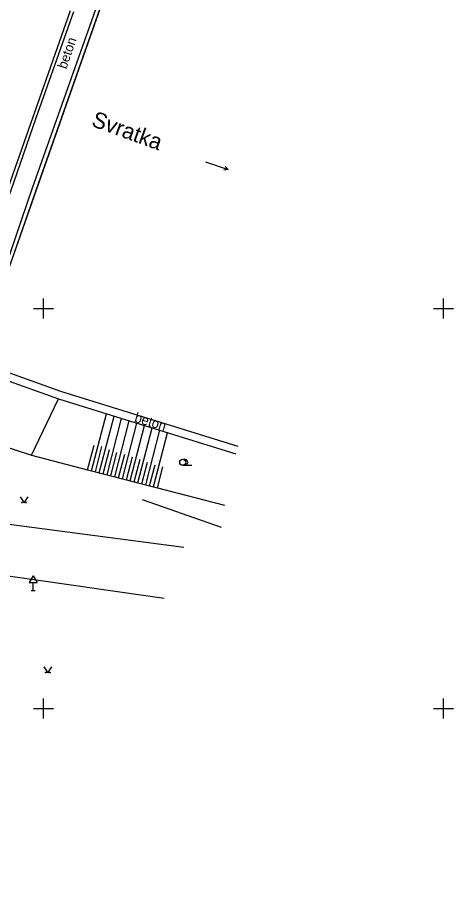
# Model space of a CAD drawing. Extents: x -599151 to -598424, y -1163476 to -1161924.
# Drawn here: x -598551.6 to -598524.4, y -1162086.9 to -1162031.8 of the extents above; entities that cross this region are included whole.
import ezdxf

# ---------------------------------------------------------------- set-up
doc = ezdxf.new("R2010")
doc.units = 0
for name, color, linetype in [('Vrstva 14', 7, 'Continuous'), ('Vrstva 17', 7, 'Continuous'), ('Vrstva 19', 7, 'Continuous'), ('Vrstva 22', 7, 'Continuous'), ('Vrstva 40', 7, 'Continuous'), ('Vrstva 41', 7, 'Continuous'), ('Vrstva 42', 7, 'Continuous'), ('Vrstva 49', 7, 'Continuous'), ('Vrstva 62', 7, 'Continuous'), ('Vrstva 63', 7, 'Continuous'), ('Vrstva 7', 7, 'Continuous')]:
    doc.layers.add(name, color=color, linetype=linetype)

msp = doc.modelspace()

# ---------------------------------------------------------------- linework, layer by layer
at = {"layer": 'Vrstva 14'}
msp.add_line((-598541.292, -1162059.805), (-598540.73, -1162059.805), dxfattribs=at)
for points in [[(-598551.464, -1162061.786), (-598551.214, -1162062.161), (-598550.964, -1162061.786)], [(-598549.981, -1162072.407), (-598549.731, -1162072.782), (-598549.481, -1162072.407)]]:
    msp.add_lwpolyline(points, dxfattribs=at)
for centre, radius in [((-598541.292, -1162059.617), 0.188), ((-598551.339, -1162062.136), 0.025), ((-598551.089, -1162062.136), 0.025), ((-598549.856, -1162072.757), 0.025), ((-598549.606, -1162072.757), 0.025)]:
    msp.add_circle(centre, radius, dxfattribs=at)
msp.add_arc((-598541.167, -1162059.617), 0.188, 249.4944, 109.0474, dxfattribs=at)
at = {"layer": 'Vrstva 17'}
for points in [[(-598537.83, -1162058.62), (-598548.91, -1162055.19), (-598554.206, -1162053.285)], [(-598554.367, -1162053.745), (-598549.065, -1162055.653), (-598537.974, -1162059.086)]]:
    msp.add_lwpolyline(points, dxfattribs=at)
at = {"layer": 'Vrstva 19'}
for p, q in [((-598550.65, -1162066.707), (-598550.9, -1162067.14)), ((-598550.65, -1162066.707), (-598550.4, -1162067.14)), ((-598550.9, -1162067.14), (-598550.4, -1162067.14)), ((-598550.775, -1162067.64), (-598550.525, -1162067.64)), ((-598550.65, -1162067.64), (-598550.65, -1162067.14))]:
    msp.add_line(p, q, dxfattribs=at)
at = {"layer": 'Vrstva 22'}
for points in [[(-598542.48, -1162019.53), (-598543.17, -1162021.17), (-598550.71, -1162042.47), (-598557.07, -1162061.1)], [(-598543.82, -1162061.94), (-598538.883, -1162063.667)]]:
    msp.add_lwpolyline(points, dxfattribs=at)
at = {"layer": 'Vrstva 40'}
msp.add_line((-598539.861, -1162040.821), (-598538.446, -1162041.319), dxfattribs=at)
msp.add_lwpolyline([(-598538.641, -1162041.118), (-598538.446, -1162041.319), (-598538.724, -1162041.354)], dxfattribs=at)
at = {"layer": 'Vrstva 41'}
for points in [[(-598546.994, -1162060.146), (-598546.066, -1162056.581)], [(-598546.51, -1162060.272), (-598545.588, -1162056.729)], [(-598546.026, -1162060.398), (-598545.112, -1162056.877)], [(-598545.542, -1162060.523), (-598544.633, -1162057.025)], [(-598545.058, -1162060.649), (-598544.155, -1162057.173)], [(-598555.66, -1162057.56), (-598550.75, -1162059.17), (-598547.236, -1162060.083)], [(-598544.574, -1162060.775), (-598543.677, -1162057.321)], [(-598544.09, -1162060.901), (-598543.199, -1162057.469)], [(-598543.606, -1162061.027), (-598542.721, -1162057.617)], [(-598543.122, -1162061.152), (-598542.242, -1162057.765)], [(-598547.236, -1162060.083), (-598546.838, -1162058.556)], [(-598546.752, -1162060.209), (-598546.342, -1162058.633)], [(-598546.268, -1162060.335), (-598545.875, -1162058.825)], [(-598545.784, -1162060.461), (-598545.402, -1162058.994)], [(-598545.3, -1162060.586), (-598544.918, -1162059.118)], [(-598544.816, -1162060.712), (-598544.442, -1162059.275)], [(-598544.332, -1162060.838), (-598543.96, -1162059.411)], [(-598543.848, -1162060.964), (-598543.496, -1162059.606)], [(-598543.364, -1162061.089), (-598543.023, -1162059.775)], [(-598542.88, -1162061.215), (-598542.541, -1162059.906)], [(-598547.236, -1162060.083), (-598546.994, -1162060.146)], [(-598546.994, -1162060.146), (-598546.752, -1162060.209)], [(-598546.752, -1162060.209), (-598546.51, -1162060.272)], [(-598546.51, -1162060.272), (-598546.268, -1162060.335)], [(-598546.268, -1162060.335), (-598546.026, -1162060.398)], [(-598546.026, -1162060.398), (-598545.784, -1162060.461)], [(-598545.784, -1162060.461), (-598545.542, -1162060.523)], [(-598545.542, -1162060.523), (-598545.3, -1162060.586)], [(-598545.3, -1162060.586), (-598545.058, -1162060.649)], [(-598545.058, -1162060.649), (-598544.816, -1162060.712)], [(-598544.816, -1162060.712), (-598544.574, -1162060.775)], [(-598544.574, -1162060.775), (-598544.332, -1162060.838)], [(-598544.332, -1162060.838), (-598544.09, -1162060.901)], [(-598544.09, -1162060.901), (-598543.848, -1162060.964)], [(-598543.848, -1162060.964), (-598543.606, -1162061.027)], [(-598543.606, -1162061.027), (-598543.364, -1162061.089)], [(-598543.364, -1162061.089), (-598543.122, -1162061.152)], [(-598543.122, -1162061.152), (-598542.88, -1162061.215)], [(-598542.88, -1162061.215), (-598538.683, -1162062.306)]]:
    msp.add_lwpolyline(points, dxfattribs=at)
at = {"layer": 'Vrstva 62'}
for p, q in [((-598550, -1162050.625), (-598550, -1162049.375)), ((-598525, -1162050.625), (-598525, -1162049.375)), ((-598550.625, -1162050), (-598549.375, -1162050)), ((-598525.625, -1162050), (-598524.375, -1162050)), ((-598550, -1162075.625), (-598550, -1162074.375)), ((-598525, -1162075.625), (-598525, -1162074.375)), ((-598550.625, -1162075), (-598549.375, -1162075)), ((-598525.625, -1162075), (-598524.375, -1162075))]:
    msp.add_line(p, q, dxfattribs=at)
at = {"layer": 'Vrstva 63'}
msp.add_lwpolyline([(-598554.358, -1162053.748), (-598550.46, -1162042.61), (-598543.036, -1162021.484), (-598542.448, -1162019.916), (-598541.867, -1162018.634), (-598541.23, -1162017.557), (-598540.798, -1162016.95), (-598540.05, -1162016.04), (-598537.59, -1162017.24), (-598531.14, -1162020.61)], dxfattribs=at)
at = {"layer": 'Vrstva 7'}
msp.add_line((-598550.75, -1162059.17), (-598549.065, -1162055.653), dxfattribs=at)
for points in [[(-598542.32, -1162019.61), (-598542.68, -1162020.47), (-598550.46, -1162042.61), (-598556.99, -1162061.22), (-598557.47, -1162062.64)], [(-598548.319, -1162031.383), (-598550.669, -1162038.044), (-598552.049, -1162042.014), (-598552.959, -1162044.584), (-598555.259, -1162051.174), (-598558.601, -1162060.571), (-598558.661, -1162060.801), (-598559.098, -1162062.033), (-598559.769, -1162063.904), (-598561.639, -1162069.435), (-598566.539, -1162083.284), (-598568.529, -1162088.954)], [(-598548.13, -1162031.45), (-598550.48, -1162038.11), (-598551.86, -1162042.08), (-598552.77, -1162044.65), (-598555.07, -1162051.24), (-598558.41, -1162060.63), (-598558.47, -1162060.86), (-598558.91, -1162062.1), (-598559.58, -1162063.97), (-598561.45, -1162069.5), (-598566.35, -1162083.35), (-598568.34, -1162089.02)], [(-598557.08, -1162062.83), (-598541.23, -1162064.93)], [(-598542.45, -1162068.14), (-598552.2, -1162066.73), (-598555.64, -1162071.6)]]:
    msp.add_lwpolyline(points, dxfattribs=at)

# ---------------------------------------------------------------- texts
at = {"layer": 'Vrstva 42'}
msp.add_text('Svratka', height=1, rotation=339.9969, dxfattribs=at).set_placement((-598547.056, -1162038.575))
at = {"layer": 'Vrstva 49'}
for rotation, p in [(71.0731, (-598548.572, -1162035.069)), (342.7992, (-598544.354, -1162057.069))]:
    msp.add_text('beton', height=0.6, rotation=rotation, dxfattribs=at).set_placement(p)

doc.saveas('drawing.dxf')
